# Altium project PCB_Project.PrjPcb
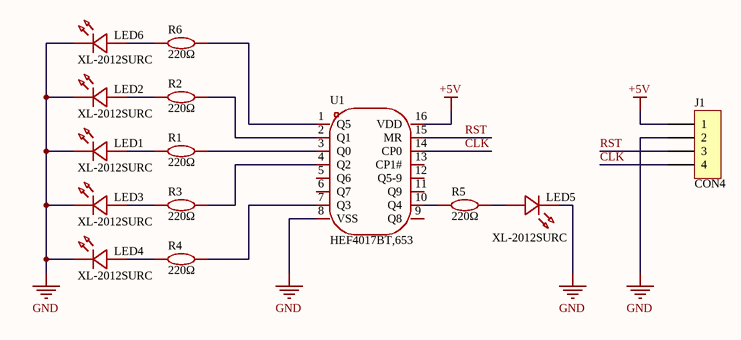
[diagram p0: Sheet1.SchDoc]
1 sheet, 14 parts. Net scope: global (net labels, ports and power ports of the same name join across sheets).
Board file: PCB2.PcbDoc

## Sheet Sheet1.SchDoc
size A4; SheetNumber: 1; SheetTotal: 1

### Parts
J1  CON4  [SIP4]
LED1  XL-2012SURC  [LED0805-RD_RED]
LED2  XL-2012SURC  [LED0805-RD_RED]
LED3  XL-2012SURC  [LED0805-RD_RED]
LED4  XL-2012SURC  [LED0805-RD_RED]
LED5  XL-2012SURC  [LED0805-RD_RED]
LED6  XL-2012SURC  [LED0805-RD_RED]
R1  220Ω  [R0603]
R2  220Ω  [R0603]
R3  220Ω  [R0603]
R4  220Ω  [R0603]
R5  220Ω  [R0603]
R6  220Ω  [R0603]
U1  HEF4017BT,653  [SOP-16_L10.0-W3.9-P1.27-LS6.0-BL]

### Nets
+5V: J1.1 U1.16(VDD)
GND: J1.2 LED1.1(K) LED2.1(K) LED3.1(K) LED4.1(K) LED5.1(K) LED6.1(K) U1.8(VSS)
CLK: J1.4 U1.14(CP0)
RST: J1.3 U1.15(MR)
NetLED1_2: LED1.2(A) R1.1
NetLED2_2: LED2.2(A) R2.1
NetLED3_2: LED3.2(A) R3.1
NetLED4_2: LED4.2(A) R4.1
NetLED5_2: LED5.2(A) R5.2
NetLED6_2: LED6.2(A) R6.1
NetR1_2: R1.2 U1.3(Q0)
NetR2_2: R2.2 U1.2(Q1)
NetR3_2: R3.2 U1.4(Q2)
NetR4_2: R4.2 U1.7(Q3)
NetR5_1: R5.1 U1.10(Q4)
NetR6_2: R6.2 U1.1(Q5)

Not connected (* = marked no-connect by the designer): U1 5(Q6) 6(Q7) 9(Q8) 11(Q9) 12(Q5-9) 13(CP1#)

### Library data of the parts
J1 = CON4: Connector
LED1-LED6 = XL-2012SURC: Manufacturer: XINGLIGHT(成兴光); Add into BOM: yes; Emitted Color: 红色; Power Dissipation: 55mW; Forward Current: 25mA; Dominant Wavelength: 617nm~621nm; Peak Wavelength: 623nm; Lens Color: 无色透明透镜; Viewing Angle: 120°; Mounting Sytle: 正贴
R1-R6 = 0603WAF2200T5E: Manufacturer: UNI-ROYAL(厚声); Add into BOM: yes; Tolerance: ±1%; Power(Watts): 100mW; Overload Voltage (Max): 75V; Temperature Coefficient: ±100ppm/℃
U1 = HEF4017BT,653: Manufacturer: Nexperia(安世); Add into BOM: yes; Logic Type: 10分频; Direction: 向上计数器; Voltage - Supply: 4.5V~15.5V; Number of Elements: 1; Trigger Type: 上升沿；下降沿; Reset: 异步; Timing: 同步; Count Rate: 30MHz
